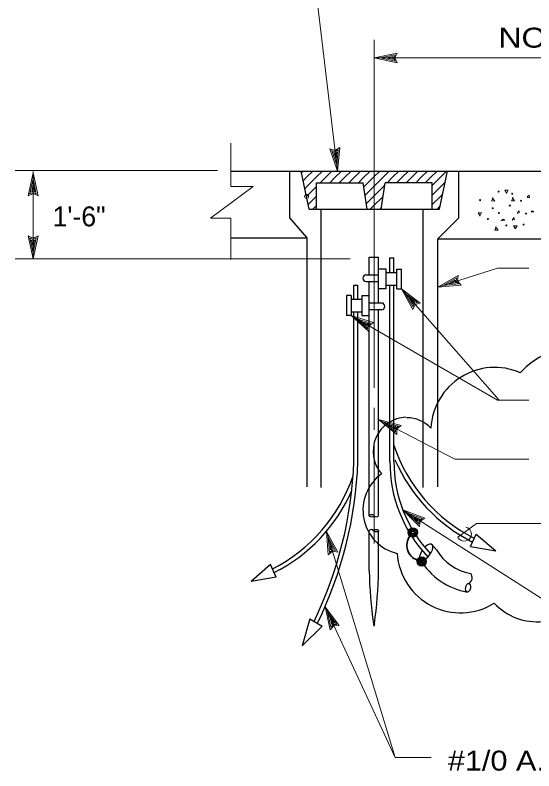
# Model space of a CAD drawing. Extents: x -39.6 to 16.1, y -17.6 to 34.
# Drawn here: x -11.635 to -8.378, y -3.13 to 1.61 of the extents above; entities that cross this region are included whole.
import ezdxf
from ezdxf.enums import TextEntityAlignment as Align

# ---------------------------------------------------------------- set-up
doc = ezdxf.new("R2010")
doc.units = 0
doc.header["$LTSCALE"] = 0.05
doc.header["$PDMODE"] = 32
doc.header["$PDSIZE"] = 0.025
doc.layers.add('1', color=7, linetype='Continuous', lineweight=13)
doc.layers.add('2', color=7, linetype='Continuous', lineweight=13)

msp = doc.modelspace()

# ---------------------------------------------------------------- linework, layer by layer
at = {"layer": '1'}
for p, q in [((-9.38021, -0.72858), (-9.38021, 1.45442)), ((-9.38021, 1.34142), (-9.23621, 1.37242)), ((-9.38021, 1.34142), (-6.38321, 1.34142)), ((-9.38021, 1.34142), (-9.23621, 1.31042)), ((-9.34321, 1.34142), (-9.24921, 1.36142)), ((-9.34321, 1.34142), (-9.24921, 1.32142)), ((-9.30721, 1.34142), (-9.26221, 1.35142)), ((-9.30721, 1.34142), (-9.26221, 1.33242)), ((-9.26221, 1.35142), (-9.26621, 1.34142)), ((-9.26621, 1.34142), (-9.26221, 1.33242)), ((-9.24921, 1.36142), (-9.25821, 1.34142)), ((-9.25821, 1.34142), (-9.24921, 1.32142)), ((-10.28021, 0.53542), (-10.28021, 0.80642)), ((-9.61521, 0.66942), (-9.64621, 0.76042)), ((-9.64621, 0.76042), (-9.62521, 0.75342)), ((-9.62521, 0.75342), (-9.60721, 0.76442)), ((-9.61521, 0.66942), (-9.60721, 0.76442)), ((-9.61121, 0.63242), (-9.59721, 0.77942)), ((-9.62021, 0.70442), (-9.63521, 0.74842)), ((-9.63521, 0.74842), (-9.62421, 0.74542)), ((-9.62421, 0.74542), (-9.61621, 0.75042)), ((-9.62021, 0.70442), (-9.61621, 0.75042)), ((-10.36521, 0.63542), (-11.63521, 0.63542)), ((-11.52221, 0.62042), (-11.55321, 0.47642)), ((-11.52221, 0.08142), (-11.52221, 0.62942)), ((-11.52221, 0.62042), (-11.49121, 0.47642)), ((-9.83621, 0.62142), (-9.82621, 0.63242)), ((-9.80521, 0.59342), (-9.76621, 0.63242)), ((-9.74521, 0.59342), (-9.70621, 0.63242)), ((-9.68521, 0.59342), (-9.64621, 0.63242)), ((-9.62521, 0.59342), (-9.58621, 0.63242)), ((-9.56521, 0.59342), (-9.52621, 0.63242)), ((-9.50521, 0.59342), (-9.46621, 0.63242)), ((-9.44521, 0.59342), (-9.40621, 0.63242)), ((-9.38521, 0.59342), (-9.34621, 0.63242)), ((-9.32521, 0.59342), (-9.28621, 0.63242)), ((-9.26521, 0.59342), (-9.22621, 0.63242)), ((-9.20521, 0.59342), (-9.16621, 0.63242)), ((-9.14521, 0.59342), (-9.10621, 0.63242)), ((-9.08521, 0.59342), (-9.04621, 0.63242)), ((-9.02521, 0.59342), (-8.98621, 0.63242)), ((-8.96521, 0.59342), (-8.92621, 0.63242)), ((-11.52221, 0.58342), (-11.54221, 0.48942)), ((-11.52221, 0.58342), (-11.50221, 0.48942)), ((-9.82621, 0.57142), (-9.80521, 0.59342)), ((-9.80521, 0.53342), (-9.74521, 0.59342)), ((-9.72021, 0.55842), (-9.68521, 0.59342)), ((-9.66021, 0.55842), (-9.62521, 0.59342)), ((-9.60021, 0.55842), (-9.56521, 0.59342)), ((-9.54021, 0.55842), (-9.50521, 0.59342)), ((-9.48021, 0.55842), (-9.44521, 0.59342)), ((-9.44521, 0.53342), (-9.38521, 0.59342)), ((-9.38521, 0.53342), (-9.32521, 0.59342)), ((-9.30021, 0.55842), (-9.26521, 0.59342)), ((-9.24021, 0.55842), (-9.20521, 0.59342)), ((-9.18021, 0.55842), (-9.14521, 0.59342)), ((-9.12021, 0.55842), (-9.08521, 0.59342)), ((-9.06021, 0.55842), (-9.02521, 0.59342)), ((-9.01721, 0.54142), (-8.96521, 0.59342)), ((-11.52221, 0.54742), (-11.53121, 0.50242)), ((-11.52221, 0.54742), (-11.51221, 0.50242)), ((-10.40821, 0.33642), (-10.14021, 0.53542)), ((-10.28021, 0.53542), (-10.14021, 0.53542)), ((-9.81521, 0.52242), (-9.80521, 0.53342)), ((-9.80521, 0.47342), (-9.74521, 0.53342)), ((-9.74521, 0.53342), (-9.74321, 0.53542)), ((-9.44521, 0.53242), (-9.44521, 0.53342)), ((-9.43721, 0.48142), (-9.38521, 0.53342)), ((-9.38521, 0.47342), (-9.32521, 0.53342)), ((-9.32521, 0.53342), (-9.31321, 0.54542)), ((-9.01721, 0.48142), (-8.96521, 0.53342)), ((-8.96521, 0.53342), (-8.93621, 0.56242)), ((-11.52221, 0.49842), (-11.54221, 0.48942)), ((-11.52221, 0.50642), (-11.53121, 0.50242)), ((-11.51221, 0.50242), (-11.52221, 0.50642)), ((-11.50221, 0.48942), (-11.52221, 0.49842)), ((-9.74521, 0.47342), (-9.74321, 0.47542)), ((-9.32521, 0.47342), (-9.32421, 0.47542)), ((-8.96521, 0.47342), (-8.95221, 0.48742)), ((-9.79521, 0.42342), (-9.74521, 0.47342)), ((-9.42921, 0.42942), (-9.38521, 0.47342)), ((-9.38521, 0.41342), (-9.32521, 0.47342)), ((-9.01721, 0.42142), (-8.96521, 0.47342)), ((-9.76521, 0.39342), (-9.74521, 0.41342)), ((-9.74521, 0.41342), (-9.74321, 0.41542)), ((-9.40521, 0.39342), (-9.38521, 0.41342)), ((-9.34521, 0.39342), (-9.33521, 0.40442)), ((-8.98521, 0.39342), (-8.96821, 0.41142)), ((-10.40821, 0.33642), (-10.28021, 0.33642)), ((-10.28021, 0.07642), (-10.28021, 0.33642)), ((-11.52221, 0.08142), (-11.55321, 0.22542)), ((-11.52221, 0.11842), (-11.54221, 0.21242)), ((-11.54221, 0.21242), (-11.52221, 0.20342)), ((-11.52221, 0.15442), (-11.53221, 0.19942)), ((-11.53221, 0.19942), (-11.52221, 0.19542)), ((-11.52221, 0.08142), (-11.49121, 0.22542)), ((-11.52221, 0.11842), (-11.50221, 0.21242)), ((-11.52221, 0.20342), (-11.50221, 0.21242)), ((-11.52221, 0.15442), (-11.51321, 0.19942)), ((-11.52221, 0.19542), (-11.51321, 0.19942)), ((-9.53221, 0.08142), (-11.63521, 0.08142)), ((-8.60721, 0.02342), (-8.98221, -0.09658)), ((-8.60721, 0.02342), (-8.41021, 0.02342)), ((-8.98221, -0.09658), (-8.85421, -0.02358)), ((-8.94721, -0.08558), (-8.86321, -0.03758)), ((-8.86321, -0.03758), (-8.86621, -0.05958)), ((-8.98221, -0.09658), (-8.83521, -0.08258)), ((-8.94721, -0.08558), (-8.85121, -0.07558)), ((-8.91221, -0.07458), (-8.87321, -0.05158)), ((-8.91221, -0.07458), (-8.86721, -0.06958)), ((-8.87321, -0.05158), (-8.87321, -0.06158)), ((-8.87321, -0.06158), (-8.86721, -0.06958)), ((-8.86621, -0.05958), (-8.85121, -0.07558)), ((-8.59621, -0.80558), (-9.21021, -0.10758)), ((-9.21021, -0.10758), (-9.09221, -0.19558)), ((-9.21021, -0.10758), (-9.13821, -0.23658)), ((-9.18621, -0.13558), (-9.10821, -0.19258)), ((-9.18621, -0.13558), (-9.13821, -0.21958)), ((-9.16221, -0.16258), (-9.13921, -0.20258)), ((-9.16221, -0.16258), (-9.12521, -0.18958)), ((-9.12521, -0.18958), (-9.13521, -0.19358)), ((-9.13521, -0.19358), (-9.13921, -0.20258)), ((-9.12921, -0.19958), (-9.13821, -0.21958)), ((-9.10821, -0.19258), (-9.12921, -0.19958)), ((-8.60721, -0.80558), (-9.52621, -0.27358)), ((-9.52621, -0.27358), (-9.38621, -0.31858)), ((-9.52621, -0.27358), (-9.41721, -0.37258)), ((-9.49421, -0.29258), (-9.40321, -0.32158)), ((-9.49421, -0.29258), (-9.42321, -0.35658)), ((-9.46321, -0.31058), (-9.42821, -0.34058)), ((-9.46321, -0.31058), (-9.41921, -0.32358)), ((-9.42721, -0.33058), (-9.42821, -0.34058)), ((-9.41921, -0.32358), (-9.42721, -0.33058)), ((-9.40321, -0.32158), (-9.42021, -0.33458)), ((-9.42021, -0.33458), (-9.42321, -0.35658)), ((-8.60721, -0.80558), (-8.41021, -0.80558)), ((-9.38021, -0.99158), (-9.38021, -0.85258)), ((-8.87382, -1.17427), (-9.35321, -0.92558)), ((-9.35321, -0.92558), (-9.21121, -0.96458)), ((-9.35321, -0.92558), (-9.23921, -1.01958)), ((-9.32021, -0.94258), (-9.22821, -0.96858)), ((-9.32021, -0.94258), (-9.24621, -1.00358)), ((-9.28821, -0.95958), (-9.25221, -0.98758)), ((-9.28821, -0.95958), (-9.24421, -0.97058)), ((-9.24421, -0.97058), (-9.25221, -0.97758)), ((-9.25221, -0.97758), (-9.25221, -0.98758)), ((-9.24521, -0.98158), (-9.24621, -1.00358)), ((-9.22821, -0.96858), (-9.24521, -0.98158)), ((-9.38021, -1.70358), (-9.38021, -1.07858)), ((-8.87382, -1.17427), (-8.41021, -1.17427)), ((-9.20121, -1.49358), (-9.09621, -1.59758)), ((-9.17021, -1.51358), (-9.08021, -1.54758)), ((-9.17021, -1.51358), (-9.10121, -1.58058)), ((-9.13921, -1.53258), (-9.10621, -1.56458)), ((-9.13921, -1.53258), (-9.09621, -1.54858)), ((-9.10521, -1.55458), (-9.10621, -1.56458)), ((-9.09621, -1.54858), (-9.10521, -1.55458)), ((-9.09821, -1.55958), (-9.10121, -1.58058)), ((-9.08021, -1.54758), (-9.09821, -1.55958)), ((-8.85548, -1.6635), (-8.73822, -1.57821)), ((-8.73822, -1.57821), (-7.89371, -1.57821)), ((-9.24821, -3.04658), (-9.68121, -1.62858)), ((-9.68121, -1.62858), (-9.60921, -1.75758)), ((-9.68121, -1.62858), (-9.66921, -1.77558)), ((-9.67021, -1.66358), (-9.62421, -1.74758)), ((-9.67021, -1.66358), (-9.66221, -1.75958)), ((-9.66021, -1.69858), (-9.65521, -1.74358)), ((-9.66021, -1.69858), (-9.63721, -1.73858)), ((-9.64521, -1.74558), (-9.66221, -1.75958)), ((-9.64821, -1.73758), (-9.65521, -1.74358)), ((-9.63721, -1.73858), (-9.64821, -1.73758)), ((-9.62421, -1.74758), (-9.64521, -1.74558)), ((-9.24821, -3.04658), (-9.68921, -2.10158)), ((-9.68921, -2.10158), (-9.60021, -2.21858)), ((-9.68921, -2.10158), (-9.65621, -2.24558)), ((-9.67321, -2.13558), (-9.61521, -2.21158)), ((-9.67321, -2.13558), (-9.65221, -2.22858)), ((-9.65821, -2.16758), (-9.64721, -2.21258)), ((-9.65821, -2.16758), (-9.63021, -2.20458)), ((-9.63721, -2.21258), (-9.65221, -2.22858)), ((-9.64121, -2.20458), (-9.64721, -2.21258)), ((-9.63021, -2.20458), (-9.64121, -2.20458)), ((-9.61521, -2.21158), (-9.63721, -2.21258)), ((-9.24821, -3.04658), (-9.02321, -3.04658))]:
    msp.add_line(p, q, dxfattribs=at)
at = {"layer": '1', "lineweight": 25}
for p, q in [((-10.28021, 0.63242), (-3.87821, 0.63242)), ((-9.91021, 0.33942), (-9.91021, 0.63242)), ((-9.78921, 0.39342), (-9.83921, 0.63242)), ((-8.97121, 0.39342), (-8.92121, 0.63242)), ((-8.85021, 0.33942), (-8.85021, 0.63242)), ((-9.74321, 0.39342), (-9.74321, 0.55842)), ((-9.74321, 0.55842), (-9.44921, 0.55842)), ((-9.42421, 0.39342), (-9.44921, 0.55842)), ((-9.33621, 0.39342), (-9.31121, 0.55842)), ((-9.01721, 0.55842), (-9.31121, 0.55842)), ((-9.01721, 0.39342), (-9.01721, 0.55842)), ((-9.78921, 0.39342), (-8.97121, 0.39342)), ((-9.71421, -1.35258), (-9.71421, 0.39342)), ((-9.07421, -1.35258), (-9.07421, 0.39342)), ((-9.80221, 0.21242), (-9.91021, 0.33942)), ((-8.98221, 0.20742), (-8.85021, 0.33942)), ((-10.28021, 0.21242), (-9.80221, 0.21242)), ((-9.80221, -1.34958), (-9.80221, 0.21242)), ((-8.98221, 0.20742), (-6.38321, 0.20742)), ((-8.98221, -1.34958), (-8.98221, 0.20742)), ((-9.41221, 0.09242), (-9.35321, 0.09242)), ((-9.41221, -0.01858), (-9.41221, 0.09242)), ((-9.35321, -0.19758), (-9.35321, 0.09242)), ((-9.28221, 0.08742), (-9.25721, 0.08742)), ((-9.28221, -0.00458), (-9.28221, 0.08742)), ((-9.25721, -0.00158), (-9.25721, 0.08742)), ((-9.23921, -0.10758), (-9.23921, 0.01742)), ((-9.23921, 0.01742), (-9.21021, 0.01742)), ((-9.21021, -0.10758), (-9.21021, 0.01742)), ((-9.43321, -0.01858), (-9.35421, -0.01858)), ((-9.30621, -0.00358), (-9.23921, -0.00358)), ((-9.50821, -0.08258), (-9.48321, -0.08258)), ((-9.50821, -0.17558), (-9.50821, -0.08258)), ((-9.48321, -0.17558), (-9.48321, -0.08258)), ((-9.43321, -0.06058), (-9.35421, -0.06058)), ((-9.41221, -1.52958), (-9.41221, -0.06158)), ((-9.30621, -0.08258), (-9.23921, -0.08258)), ((-9.28221, -1.18958), (-9.28221, -0.08458)), ((-9.25721, -1.18958), (-9.25721, -0.08258)), ((-9.30621, -0.10758), (-9.35321, -0.10758)), ((-9.23921, -0.10758), (-9.21021, -0.10758)), ((-9.55521, -0.14858), (-9.55521, -0.27358)), ((-9.52621, -0.14858), (-9.55521, -0.14858)), ((-9.52621, -0.14858), (-9.52621, -0.27358)), ((-9.45921, -0.17358), (-9.52621, -0.17358)), ((-9.45921, -0.14858), (-9.41221, -0.14858)), ((-9.33221, -0.19558), (-9.41121, -0.19558)), ((-9.52621, -0.27358), (-9.55521, -0.27358)), ((-9.45921, -0.25258), (-9.52621, -0.25258)), ((-9.50821, -1.18958), (-9.50821, -0.25358)), ((-9.48321, -1.18958), (-9.48321, -0.25158)), ((-9.33221, -0.23758), (-9.41121, -0.23758)), ((-9.35321, -1.52958), (-9.35321, -0.23958)), ((-9.41221, -1.87558), (-9.41221, -1.62358)), ((-9.35321, -1.87558), (-9.35321, -1.62358)), ((-9.02121, -1.70858), (-8.99021, -1.74358)), ((-8.7763, -1.72383), (-8.6173, -1.74983)), ((-9.99521, -1.91558), (-10.15421, -1.94158)), ((-9.78521, -2.17758), (-9.70721, -2.22258)), ((-9.38621, -2.20858), (-9.38321, -2.22158)), ((-9.37921, -2.20858), (-9.38321, -2.22158))]:
    msp.add_line(p, q, dxfattribs=at)
at = {"layer": '1'}
for points in [[(-9.76721, 1.94842), (-9.61121, 0.63242), (-9.65921, 0.77142)], [(-9.23621, 1.37242), (-9.25021, 1.34142), (-9.23621, 1.31042)], [(-9.65921, 0.77142), (-9.62621, 0.76142), (-9.59721, 0.77942)], [(-11.49121, 0.47642), (-11.52221, 0.49042), (-11.55321, 0.47642)], [(-11.55321, 0.22542), (-11.52221, 0.21142), (-11.49121, 0.22542)], [(-8.85421, -0.02358), (-8.85821, -0.05658), (-8.83521, -0.08258)], [(-9.09221, -0.19558), (-9.12421, -0.20558), (-9.13821, -0.23658)], [(-9.38621, -0.31858), (-9.41321, -0.33858), (-9.41721, -0.37258)], [(-9.21121, -0.96458), (-9.23821, -0.98558), (-9.23921, -1.01958)], [(-8.08377, -2.20527), (-9.20121, -1.49358), (-9.06321, -1.54458)], [(-9.06321, -1.54458), (-9.09121, -1.56358), (-9.09621, -1.59758)], [(-9.60921, -1.75758), (-9.64321, -1.75258), (-9.66921, -1.77558)], [(-9.60021, -2.21858), (-9.63421, -2.21958), (-9.65621, -2.24558)]]:
    msp.add_lwpolyline(points, dxfattribs=at)
msp.add_lwpolyline([(-9.83921, 0.63242), (-9.78921, 0.39342), (-9.74321, 0.39342), (-9.74321, 0.55842), (-9.44921, 0.55842), (-9.42421, 0.39342), (-9.33621, 0.39342), (-9.31121, 0.55842), (-9.01721, 0.55842), (-9.01721, 0.39342), (-8.97121, 0.39342), (-8.92121, 0.63242)], close=True, dxfattribs=at)
at = {"layer": '1', "lineweight": 25}
for points in [[(-9.30621, -0.10758), (-9.30621, 0.01742), (-9.35321, 0.01742)], [(-9.45921, -0.14858), (-9.45921, -0.27358), (-9.41221, -0.27358)], [(-8.7763, -1.72383), (-8.7403, -1.64483), (-8.6173, -1.74983)], [(-9.99521, -1.91558), (-10.03121, -1.83658), (-10.15421, -1.94158)], [(-9.78521, -2.17758), (-9.83321, -2.34558), (-9.70721, -2.22258)]]:
    msp.add_lwpolyline(points, dxfattribs=at)
for centre, radius in [((-9.13846, -1.63477), 0.02891), ((-9.13846, -1.63477), 0.02242), ((-9.13846, -1.63477), 0.01644), ((-9.13846, -1.63477), 0.0083), ((-9.08246, -1.81677), 0.02891), ((-9.08246, -1.81677), 0.02242), ((-9.08246, -1.81677), 0.01644), ((-9.08246, -1.81677), 0.0083)]:
    msp.add_circle(centre, radius, dxfattribs=at)
for centre, radius, start, end in [((-8.08232, -0.98618), 0.52021, 49.25934, 137.21745), ((-8.62395, -1.0004), 0.4008, 66.49904, 177.19519), ((-9.17376, -1.12575), 0.21389, 92.1212, 221.34757), ((-9.17805, -1.12716), 0.2123, 43.5876, 89.77221), ((-8.28942, -0.75933), 1.02274, 198.67622, 243.15254), ((-8.28942, -0.75933), 1.04888, 203.63508, 243.15254), ((-12.01957, -1.09628), 2.51309, 334.13592, 357.87225), ((-12.01957, -1.09628), 2.53809, 334.13592, 357.87225), ((-8.42133, -1.19331), 0.86096, 179.75224, 223.46526), ((-8.42133, -1.19331), 0.83587, 179.75224, 223.46526), ((-10.4821, -0.95108), 1.02274, 296.84746, 341.32378), ((-9.17168, -1.49459), 0.2797, 125.55807, 256.64033), ((-10.4821, -0.95108), 1.04888, 296.84746, 336.36492), ((-9.36721, -1.51915), 0.01746, 216.68235, 323.31765), ((-9.39821, -1.63401), 0.01746, 36.68235, 143.31765), ((-8.72285, -1.58646), 0.3096, 210.44834, 260.14123), ((-8.83915, -1.74135), 0.39797, 183.65494, 302.07617), ((-8.72285, -1.58646), 0.42845, 210.44834, 260.14123), ((-6.62265, -1.82529), 2.79001, 181.03278, 187.89619), ((-12.14277, -1.82529), 2.79001, 352.10381, 358.96722), ((-8.8056, -1.91891), 0.04014, 297.28052, 42.91111), ((-8.3569, -1.82236), 0.37288, 223.40398, 327.48388)]:
    msp.add_arc(centre, radius, start, end, dxfattribs=at)
at = {"layer": '1'}
msp.add_arc((-8.81514, -1.64467), 0.04452, 205.02418, 78.69149, dxfattribs=at)
at = {"layer": '1', "lineweight": 35}
msp.add_arc((-9.07933, -1.71606), 0.09659, 142.74187, 251.35619, dxfattribs=at)
at = {"layer": '1', "lineweight": 25}
for centre, major_axis, ratio, start_param, end_param in [((-9.43321, -0.03958), (0, -0.021), 0.861056, 3.1415927, 6.2831853), ((-9.33221, -0.21658), (0, 0.021), 0.861056, 3.1415927, 6.2831853), ((-9.05421, -1.75808), (0.035, 0.0485), 0.460126, 1.7221698, 7.5061396)]:
    msp.add_ellipse(centre, major_axis=major_axis, ratio=ratio, start_param=start_param, end_param=end_param, dxfattribs=at)
for centre, major_axis, ratio in [((-9.39671, -1.53008), (0.0155, -0.0005), 0.501832), ((-9.36871, -1.62308), (0.0155, -0.0005), 0.501832), ((-8.79171, -1.98158), (0.0045, 0.027), 0.536446)]:
    msp.add_ellipse(centre, major_axis=major_axis, ratio=ratio, dxfattribs=at)
at = {"layer": '1'}
msp.add_point((-9.80521, 0.47342), dxfattribs=at)
at = {"layer": '2'}
msp.add_line((-8.42021, 0.47042), (-8.40821, 0.48042), dxfattribs=at)
for points in [[(-8.55121, 0.49542), (-8.56121, 0.51242), (-8.53921, 0.51242), (-8.55121, 0.49142)], [(-8.40821, 0.48142), (-8.40521, 0.46642), (-8.42021, 0.46642)], [(-8.63421, 0.46442), (-8.64421, 0.44442), (-8.62321, 0.44242), (-8.63921, 0.46442)], [(-8.50921, 0.46642), (-8.51921, 0.44642), (-8.49921, 0.44442), (-8.51421, 0.46642)], [(-8.39521, 0.37542), (-8.38821, 0.38342), (-8.37921, 0.37542), (-8.39321, 0.37342)], [(-8.71821, 0.35342), (-8.72821, 0.37042), (-8.70621, 0.37042), (-8.71821, 0.34942)], [(-8.58021, 0.32342), (-8.57021, 0.32942), (-8.56121, 0.32342), (-8.58521, 0.31942)], [(-8.49621, 0.27242), (-8.50621, 0.28942), (-8.48421, 0.28942), (-8.49621, 0.26942)], [(-8.61421, 0.28242), (-8.62421, 0.26242), (-8.60321, 0.26042), (-8.61921, 0.28242)]]:
    msp.add_lwpolyline(points, dxfattribs=at)
for points in [[(-8.48421, 0.36642), (-8.47421, 0.38342), (-8.46921, 0.37142)], [(-8.51421, 0.32342), (-8.50421, 0.34042), (-8.49921, 0.32842)]]:
    msp.add_lwpolyline(points, close=True, dxfattribs=at)
for centre in [(-8.59971, 0.50317), (-8.51421, 0.48967), (-8.71621, 0.44967), (-8.45871, 0.44617), (-8.63671, 0.39917), (-8.52921, 0.41567), (-8.66721, 0.33167), (-8.59821, 0.36867), (-8.42821, 0.36517), (-8.55121, 0.29117), (-8.44321, 0.29617)]:
    msp.add_circle(centre, 0.00325, dxfattribs=at)

# ---------------------------------------------------------------- texts
at = {"layer": '1', "width": 1.2}
msp.add_text('NOT LESS THAN', height=0.125, dxfattribs=at).set_placement((-7.80371, 1.40642), align=Align.CENTER)
at = {"layer": '1'}
msp.add_text('1\'-6"', height=0.125, dxfattribs=at).set_placement((-11.23371, 0.28542), align=Align.CENTER)
at = {"layer": '1', "width": 1.15}
msp.add_text('#1/0 A.W.G. BARE', height=0.125, dxfattribs=at).set_placement((-8.91821, -3.12858))

doc.saveas('drawing.dxf')
